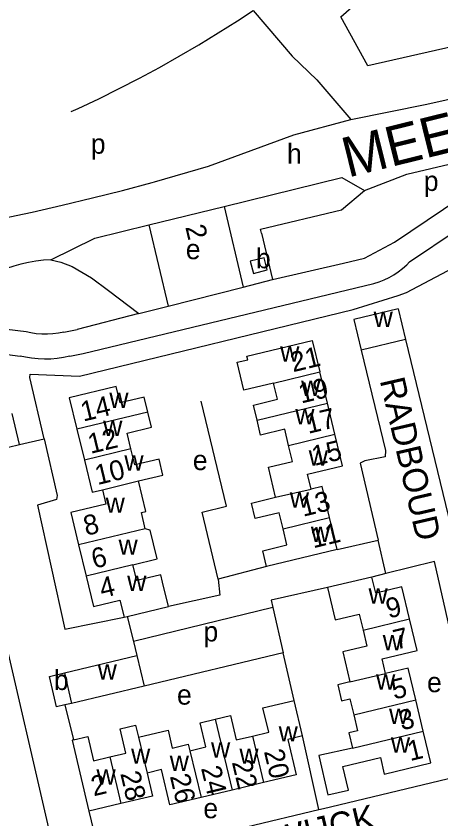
# Model space of a CAD drawing. Extents: x 157646 to 159241, y 379213 to 381217.
# Drawn here: x 158162.1 to 158247.5, y 380777.5 to 380938.8 of the extents above; entities that cross this region are included whole.
import ezdxf

# ---------------------------------------------------------------- set-up
doc = ezdxf.new("R2010")
doc.units = 0
for name, color, linetype in [('BLT_Basislijn', 7, 'Continuous'), ('BLT_Bebouwing', 7, 'Continuous'), ('BLT_Centroide', 7, 'Continuous'), ('BLT_Huisnummer', 7, 'Continuous'), ('BLT_Huisnummer_ tussenligend', 7, 'Continuous'), ('BLT_Onderverdeling_panden', 7, 'Continuous'), ('BLT_Straatnaam', 7, 'Continuous'), ('BLT_Straatnaam_hoofdweg', 7, 'Continuous'), ('BLT_Vlakafsluiter', 7, 'Continuous')]:
    doc.layers.add(name, color=color, linetype=linetype)

msp = doc.modelspace()

# ---------------------------------------------------------------- linework, layer by layer
at = {"layer": 'BLT_Basislijn'}
for p, q in [((158203.91, 380900.59), (158227.6, 380906.42)), ((158227.5, 380899.9), (158232.12, 380903.76)), ((158238.17, 380893.44), (158251.44, 380902.38)), ((158188.79, 380896.87), (158203.91, 380900.59)), ((158203.91, 380900.59), (158207.78, 380884.39)), ((158211.26, 380896.01), (158227.5, 380899.9)), ((158177.92, 380894.19), (158188.79, 380896.87)), ((158188.79, 380896.87), (158192.68, 380880.58)), ((158211.45, 380895.21), (158211.26, 380896.01)), ((158241.22, 380889.46), (158250.78, 380895.91)), ((158232.12, 380890.21), (158238.17, 380893.44)), ((158169.12, 380889.88), (158171.12, 380889.4)), ((158227.92, 380889.16), (158232.12, 380890.21)), ((158171.12, 380889.4), (158173.42, 380888.5)), ((158173.42, 380888.5), (158177.29, 380886.26)), ((158213.69, 380885.88), (158227.92, 380889.16)), ((158175.58, 380871.03), (158234.03, 380885.12)), ((158177.29, 380886.26), (158180.69, 380883.7)), ((158207.78, 380884.39), (158213.69, 380885.88)), ((158180.69, 380883.7), (158186.78, 380879.1)), ((158192.68, 380880.58), (158207.78, 380884.39)), ((158186.78, 380879.1), (158192.68, 380880.58)), ((158186.78, 380879.1), (158174.41, 380875.89)), ((158164.17, 380875.36), (158160.28, 380875.86)), ((158171.7, 380875.35), (158174.41, 380875.89)), ((158150.83, 380872.15), (158162.97, 380870.5)), ((158172.94, 380870.5), (158175.58, 380871.03)), ((158162.8, 380852.77), (158167.77, 380853.86)), ((158226.66, 380831.67), (158234.89, 380833.52)), ((158236.45, 380826.81), (158234.89, 380833.52)), ((158236.45, 380826.81), (158233.64, 380826.11)), ((158213.74, 380820), (158185.7, 380813.19)), ((158213.74, 380820), (158215.83, 380810.89)), ((158184.43, 380818.22), (158185.7, 380813.19)), ((158185.7, 380813.19), (158186.41, 380810.33))]:
    msp.add_line(p, q, dxfattribs=at)
for points in [[(158281.68, 380943.57), (158282.78, 380940.14), (158232.81, 380928.81), (158227.42, 380938.7), (158290.8, 380994.41), (158296.28, 380985.19)], [(158173.18, 380919.64), (158174.61, 380920.29), (158178.74, 380922.24), (158182.84, 380924.27), (158186.9, 380926.36), (158190.92, 380928.53), (158194.91, 380930.77), (158198.85, 380933.08), (158202.76, 380935.46), (158206.62, 380937.9), (158209.74, 380939.96)], [(158209.74, 380939.96), (158217.6, 380930.76), (158222.54, 380926.06), (158229.41, 380918.03)], [(158229.41, 380918.03), (158244.68, 380921.15), (158256.32, 380923.74), (158258.59, 380924.33)], [(158189.95, 380905.56), (158200.8, 380908.71), (158217.93, 380914.98), (158229.41, 380918.03)], [(158232.12, 380903.76), (158240.65, 380907.05), (158259.98, 380911.64)], [(158097.6, 380889.5), (158103.81, 380890.01), (158110.01, 380890.6), (158116.2, 380891.27), (158122.38, 380892.01), (158128.56, 380892.84), (158134.72, 380893.75), (158140.87, 380894.73), (158147, 380895.8), (158153.12, 380896.94), (158159.23, 380898.16), (158165.32, 380899.46), (158171.4, 380900.84), (158177.45, 380902.29), (158183.49, 380903.82), (158189.5, 380905.43), (158189.95, 380905.56)], [(158211.45, 380895.21), (158213.69, 380885.88)], [(158229.9, 380879.86), (158238.93, 380882.66), (158240.62, 380883.28), (158257.08, 380892.02), (158266.49, 380893.96), (158267.45, 380893.67), (158274.06, 380864.51), (158274.34, 380863.54), (158276.33, 380863.42), (158279.27, 380850.8)], [(158169.12, 380889.88), (158167.6, 380889.78), (158166.09, 380889.6), (158164.59, 380889.35), (158163.1, 380889.01), (158161.64, 380888.6), (158160.2, 380888.11), (158158.79, 380887.55)], [(158234.03, 380885.12), (158235.08, 380885.44), (158236.1, 380885.83), (158237.09, 380886.3), (158238.04, 380886.84), (158238.95, 380887.45), (158239.81, 380888.12), (158240.63, 380888.85), (158241.22, 380889.46)], [(158167.77, 380853.86), (158164.89, 380866.19), (158164.97, 380866.86), (158174.89, 380866.51), (158229.9, 380879.86)], [(158171.7, 380875.35), (158170.64, 380875.12), (158169.53, 380874.97), (158168.4, 380874.9), (158167.28, 380874.91), (158166.16, 380875), (158165.05, 380875.17), (158164.17, 380875.36)], [(158240.4, 380873.84), (158249.53, 380836.28), (158251.78, 380834.15), (158254.68, 380834.9), (158264.9, 380837.08)], [(158172.94, 380870.5), (158171.68, 380870.23), (158170.4, 380870.04), (158169.12, 380869.93), (158167.83, 380869.9), (158166.54, 380869.94), (158165.25, 380870.07), (158163.98, 380870.28), (158162.97, 380870.5)], [(158231.51, 380871.68), (158236.36, 380851.52), (158236.31, 380850.28), (158232.22, 380849.45), (158231.3, 380849.01), (158234.89, 380833.52)], [(158202.74, 380825.7), (158199.5, 380839.17), (158204.38, 380840.34), (158199.29, 380861.48)], [(158167.77, 380853.86), (158170.4, 380842.52), (158170.27, 380841.69), (158166.39, 380840.58), (158171.93, 380815.63), (158183.81, 380818.07)], [(158212.46, 380828.25), (158202.74, 380825.7)], [(158253.84, 380795.54), (158246.19, 380829.22), (158236.45, 380826.81)], [(158202.74, 380825.7), (158203.09, 380822.49), (158192.73, 380820.22)], [(158170.71, 380766.93), (158157.33, 380824.72), (158143.35, 380821.29)], [(158224.71, 380823.99), (158213.41, 380821.48), (158213.74, 380820)], [(158215.83, 380810.89), (158187.87, 380804.21)], [(158218.02, 380801.34), (158215.83, 380810.89)], [(158171.93, 380800.41), (158173.63, 380793.38)], [(158222.97, 380779.39), (158223.89, 380779.61), (158255.5, 380787.15), (158255.66, 380787.56), (158253.84, 380795.54)], [(158222.97, 380779.39), (158219.72, 380794.19)], [(158176.77, 380779.09), (158178.24, 380772.97)], [(158178.24, 380772.97), (158179.37, 380768.98), (158222.97, 380779.39)]]:
    msp.add_lwpolyline(points, dxfattribs=at)
at = {"layer": 'BLT_Bebouwing'}
for p, q in [((158238.9, 380880.01), (158230.02, 380877.86)), ((158238.9, 380880.01), (158240.4, 380873.84)), ((158230.02, 380877.86), (158231.51, 380871.68)), ((158240.4, 380873.84), (158231.51, 380871.68)), ((158224.68, 380861.07), (158223.18, 380867.33)), ((158226.19, 380854.81), (158224.68, 380861.07)), ((158162.8, 380852.77), (158161.33, 380858.96)), ((158174.34, 380855.83), (158175.84, 380849.59)), ((158157.09, 380851.41), (158162.8, 380852.77)), ((158226.66, 380831.67), (158225.12, 380838.05)), ((158174.69, 380832.62), (158176.2, 380826.32)), ((158226.66, 380831.67), (158212.46, 380828.25)), ((158233.64, 380826.11), (158224.71, 380823.99)), ((158184.43, 380818.22), (158192.73, 380820.22)), ((158183.81, 380818.07), (158184.43, 380818.22)), ((158171.83, 380806.85), (158186.41, 380810.33)), ((158186.41, 380810.33), (158187.87, 380804.21)), ((158219.72, 380794.19), (158218.02, 380801.34)), ((158243.94, 380795.14), (158242.45, 380801.42))]:
    msp.add_line(p, q, dxfattribs=at)
msp.add_lwpolyline([(158209.2, 380889.56), (158209.84, 380887.13), (158212.59, 380887.85), (158211.96, 380890.28)], close=True, dxfattribs=at)
for points in [[(158213.85, 380865.08), (158207.92, 380863.66), (158206.57, 380869.28), (158208.7, 380869.79), (158208.53, 380870.53), (158221.65, 380873.68), (158223.18, 380867.33)], [(158188.62, 380859.26), (158187.89, 380862.29), (158183.03, 380861.12), (158182.23, 380864.42), (158172.82, 380862.15), (158174.34, 380855.83)], [(158210.55, 380857.66), (158209.82, 380860.68), (158214.63, 380861.84), (158213.85, 380865.08)], [(158185.2, 380851.85), (158184.43, 380855.05), (158189.34, 380856.24), (158188.62, 380859.26)], [(158216.89, 380852.57), (158216.11, 380855.81), (158211.27, 380854.65), (158210.55, 380857.66)], [(158221.43, 380843.79), (158220.72, 380846.77), (158227.72, 380848.45), (158226.19, 380854.81)], [(158214.29, 380842.16), (158212.84, 380848.17), (158217.67, 380849.33), (158216.89, 380852.57)], [(158186.71, 380845.42), (158191.63, 380846.61), (158190.85, 380849.82), (158185.98, 380848.64), (158185.2, 380851.85)], [(158175.84, 380849.59), (158177.39, 380843.17), (158179.46, 380843.67)], [(158188.07, 380835.83), (158187.3, 380839.06), (158188.19, 380839.28), (158186.71, 380845.42)], [(158179.46, 380843.67), (158180.17, 380840.75), (158173.14, 380839.06), (158174.69, 380832.62)], [(158225.12, 380838.05), (158223.61, 380844.32), (158221.43, 380843.79)], [(158215.79, 380835.8), (158215.02, 380839.02), (158210.18, 380837.86), (158209.42, 380840.99), (158214.29, 380842.16)], [(158185.61, 380828.59), (158190.45, 380829.75), (158189.71, 380832.82), (158189.1, 380835.51), (158188.07, 380835.83)], [(158212.46, 380828.25), (158211.7, 380831.41), (158216.57, 380832.58), (158215.79, 380835.8)], [(158192.73, 380820.22), (158191.56, 380825.08), (158191.2, 380826.59), (158186.37, 380825.43), (158185.61, 380828.59)], [(158176.2, 380826.32), (158177.68, 380820.19), (158182.99, 380821.47), (158183.81, 380818.07)], [(158241.2, 380817.69), (158239.66, 380824.14), (158234.41, 380822.89), (158233.64, 380826.11)], [(158224.71, 380823.99), (158226.25, 380817.52), (158231.11, 380818.68), (158231.88, 380815.46)], [(158236.39, 380806.73), (158235.69, 380809.66), (158242.71, 380811.33), (158241.2, 380817.69)], [(158231.88, 380815.46), (158232.65, 380812.24), (158227.78, 380811.08), (158229.22, 380805.04)], [(158242.45, 380801.42), (158240.92, 380807.81), (158236.39, 380806.73)], [(158171.93, 380800.41), (158170.26, 380800.01), (158168.81, 380806.11), (158171.83, 380806.85)], [(158187.87, 380804.21), (158173.29, 380800.73)], [(158229.22, 380805.04), (158226.77, 380804.45), (158227.53, 380801.26), (158229.22, 380801.66), (158229.99, 380798.45)], [(158209.63, 380794.15), (158212.89, 380794.93), (158211.72, 380799.84), (158218.02, 380801.34)], [(158173.29, 380800.73), (158171.93, 380800.41)], [(158202.15, 380797.54), (158205.2, 380798.27), (158206.37, 380793.38), (158209.63, 380794.15)], [(158229.99, 380798.45), (158230.75, 380795.23), (158229, 380794.82), (158229.73, 380791.75)], [(158180.96, 380789.98), (158184.21, 380790.75), (158183.05, 380795.59), (158186.15, 380796.33), (158186.72, 380793.95)], [(158197.05, 380791.2), (158200.26, 380791.97), (158199.11, 380796.81), (158202.15, 380797.54)], [(158186.72, 380793.95), (158192.67, 380795.36), (158193.48, 380791.76), (158196.73, 380792.54), (158197.05, 380791.2)], [(158229.73, 380791.75), (158222.97, 380790.25), (158224.8, 380782.36), (158228.95, 380783.32), (158227.81, 380788.06), (158235.34, 380789.86), (158236.13, 380786.54), (158245.46, 380788.76), (158243.94, 380795.14)], [(158173.63, 380793.38), (158173.38, 380793.32), (158176.77, 380779.09)], [(158173.63, 380793.38), (158176.55, 380794.08), (158177.71, 380789.2), (158180.96, 380789.98)], [(158219.72, 380794.19), (158216.72, 380793.48), (158218.41, 380786.39), (158211.85, 380784.83)], [(158188.44, 380786.74), (158189.51, 380782.12), (158183.19, 380780.62)], [(158199.29, 380781.83), (158193.01, 380780.33), (158191.32, 380787.43), (158188.44, 380786.74)], [(158211.85, 380784.83), (158205.54, 380783.32)], [(158205.54, 380783.32), (158199.29, 380781.83)], [(158183.19, 380780.62), (158176.77, 380779.09)]]:
    msp.add_lwpolyline(points, dxfattribs=at)
at = {"layer": 'BLT_Onderverdeling_panden'}
for p, q in [((158213.85, 380865.08), (158223.18, 380867.33)), ((158210.55, 380857.66), (158224.68, 380861.07)), ((158188.62, 380859.26), (158174.34, 380855.83)), ((158216.89, 380852.57), (158226.19, 380854.81)), ((158185.2, 380851.85), (158175.84, 380849.59)), ((158179.46, 380843.67), (158186.71, 380845.42)), ((158214.29, 380842.16), (158221.43, 380843.79)), ((158215.79, 380835.8), (158225.12, 380838.05)), ((158188.07, 380835.83), (158174.69, 380832.62)), ((158185.61, 380828.59), (158176.2, 380826.32)), ((158231.88, 380815.46), (158241.2, 380817.69)), ((158171.83, 380806.85), (158173.29, 380800.73)), ((158229.22, 380805.04), (158236.39, 380806.73)), ((158229.99, 380798.45), (158242.45, 380801.42)), ((158202.15, 380797.54), (158205.54, 380783.32)), ((158229.73, 380791.75), (158243.94, 380795.14)), ((158186.72, 380793.95), (158188.44, 380786.74)), ((158209.63, 380794.15), (158211.85, 380784.83)), ((158197.05, 380791.2), (158199.29, 380781.83)), ((158180.96, 380789.98), (158183.19, 380780.62))]:
    msp.add_line(p, q, dxfattribs=at)
at = {"layer": 'BLT_Vlakafsluiter'}
for p, q in [((158227.6, 380906.42), (158232.12, 380903.76)), ((158169.12, 380889.88), (158177.92, 380894.19))]:
    msp.add_line(p, q, dxfattribs=at)

# ---------------------------------------------------------------- texts
at = {"layer": 'BLT_Centroide'}
for s, p in [('p', (158177.13, 380911.18)), ('h', (158216.57, 380909.19)), ('p', (158244.06, 380903.7)), ('e', (158196.23, 380889.99)), ('b', (158210.32, 380888.17)), ('w', (158233.98, 380876.37)), ('w', (158215.2, 380869.38)), ('w', (158219.41, 380862.5)), ('w', (158180.86, 380860.12)), ('w', (158218.23, 380856.81)), ('w', (158179.62, 380854.44)), ('w', (158220.94, 380848.5)), ('w', (158183.88, 380847.5)), ('e', (158197.64, 380847.61)), ('w', (158217.14, 380840.06)), ('w', (158180.12, 380839.03)), ('w', (158221.37, 380833.16)), ('w', (158182.71, 380830.59)), ('w', (158184.45, 380823.31)), ('w', (158232.96, 380820.78)), ('p', (158199.78, 380813.17)), ('w', (158235.82, 380811.38)), ('b', (158169.71, 380803.42)), ('w', (158178.52, 380805.53)), ('w', (158234.47, 380803.5)), ('e', (158244.72, 380802.98)), ('e', (158194.46, 380800.48)), ('w', (158237.09, 380796.59)), ('w', (158214.89, 380793.08)), ('w', (158201.3, 380789.83)), ('w', (158237.45, 380790.84)), ('w', (158185.23, 380788.59)), ('w', (158207, 380788.59)), ('w', (158193, 380787.16)), ('w', (158178.28, 380784.39)), ('e', (158199.76, 380777.65))]:
    msp.add_text(s, height=4, dxfattribs=at).set_placement(p)
at = {"layer": 'BLT_Huisnummer'}
for s, rotation, p in [('2', 283.4645, (158196.11, 380896.47)), ('21', 13.5277, (158217.8, 380867.26)), ('14', 13.5328, (158175.62, 380857.34)), ('15', 13.527, (158222.1, 380848.43)), ('10', 13.5226, (158178.49, 380844.59)), ('13', 13.5337, (158219.8, 380838.22)), ('8', 13.5226, (158176.2, 380834.39)), ('11', 13.5337, (158221.84, 380831.88)), ('4', 13.5307, (158179.4, 380821.87)), ('9', 13.4119, (158236.99, 380817.77)), ('7', 13.4119, (158238.45, 380811.5)), ('5', 13.4119, (158238.1, 380801.48)), ('1', 13.4119, (158241.31, 380789.12)), ('20', 283.4017, (158211.91, 380791.08)), ('2', 13.412, (158177.7, 380782.04)), ('28', 283.4063, (158183.04, 380786.65)), ('26', 283.4092, (158193.01, 380786.11))]:
    msp.add_text(s, height=4, rotation=rotation, dxfattribs=at).set_placement(p)
at = {"layer": 'BLT_Huisnummer_ tussenligend'}
for s, rotation, p in [('19', 13.527, (158219.42, 380860.97)), ('17', 13.527, (158220.84, 380854.88)), ('12', 13.5226, (158177.08, 380850.86)), ('6', 13.5307, (158177.79, 380827.78)), ('3', 13.4119, (158239.62, 380795.28)), ('24', 283.4092, (158199.27, 380787.72)), ('22', 283.4017, (158205.47, 380788.92))]:
    msp.add_text(s, height=4, rotation=rotation, dxfattribs=at).set_placement(p)
at = {"layer": 'BLT_Straatnaam'}
for s, rotation, p in [('RADBOUD', 283, (158235.2, 380865.64)), ('ROOSWIJCK', 13.2774, (158195.31, 380766.31))]:
    msp.add_text(s, height=5, rotation=rotation, dxfattribs=at).set_placement(p)
at = {"layer": 'BLT_Straatnaam_hoofdweg'}
msp.add_text('MEERVELDHOVENSEWEG', height=8, rotation=13.8813, dxfattribs=at).set_placement((158228.8, 380906.37))

doc.saveas('drawing.dxf')
